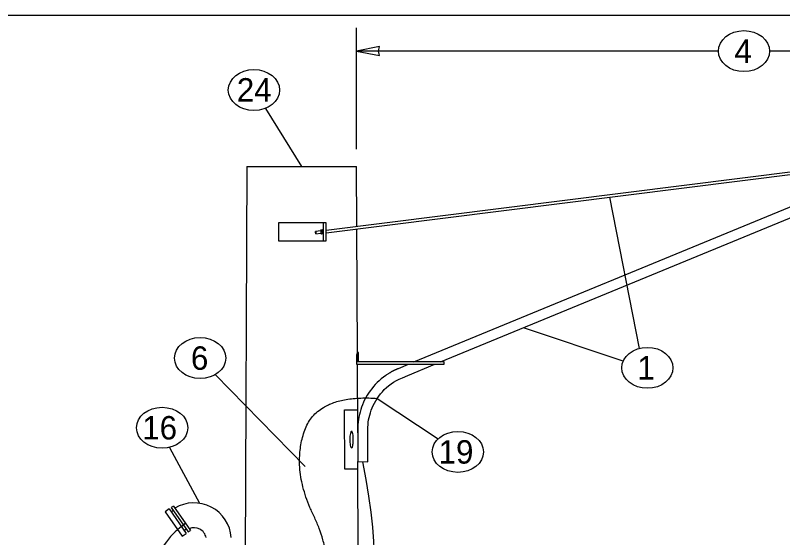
# Model space of a CAD drawing. Extents: x 99862 to 104211, y 98939 to 102076.
# Drawn here: x 100788 to 101312, y 101719 to 102076 of the extents above; entities that cross this region are included whole.
import ezdxf

# ---------------------------------------------------------------- set-up
doc = ezdxf.new("R2010")
doc.units = 0
for name, color, linetype in [('Level 1', 7, 'Continuous'), ('Level 12', 7, 'Continuous'), ('Level 15', 7, 'Continuous'), ('Level 20', 7, 'Continuous'), ('Level 32', 7, 'Continuous'), ('Level 33', 7, 'Continuous'), ('Level 34', 7, 'Continuous'), ('Level 49', 7, 'Continuous'), ('Level 7', 7, 'Continuous')]:
    doc.layers.add(name, color=color, linetype=linetype)

msp = doc.modelspace()

# ---------------------------------------------------------------- linework, layer by layer
at = {"layer": 'Level 1'}
for p, q in [((100946.45, 101972.17), (100944.21, 101433.5)), ((100946.45, 101972.17), (101021.45, 101972.17)), ((101021.62, 101931.09), (101021.45, 101972.17)), ((101021.98, 101844.89), (101021.63, 101929.52)), ((101022.23, 101790.32), (101022.01, 101837.13)), ((101023.69, 101433.5), (101022.29, 101770.61))]:
    msp.add_line(p, q, dxfattribs=at)
msp.add_lwpolyline([(99862, 99999.5), (103151, 99999.5), (103151, 102075.5), (99862, 102075.5)], close=True, dxfattribs=at)
at = {"layer": 'Level 12'}
for points, degree in [([(100904.57, 101673.7), (100910.32, 101636.13), (100995.02, 101627.02), (101007.07, 101702.96), (100977.17, 101764.49), (100993.88, 101816.64), (101035.56, 101813.83)], 2), ([(100904.2, 101728), (100894.95, 101721.58), (100879.91, 101703.82), (100865.23, 101628.33), (100967.11, 101591.05), (101052.01, 101637.94), (101025.75, 101770.54)], 3)]:
    msp.add_open_spline(points, degree=degree, dxfattribs=at)
at = {"layer": 'Level 15'}
for p, q in [((101021.45, 101984.17), (101021.45, 102067.04)), ((101268.47, 102051.04), (101021.45, 102051.04)), ((101548.64, 102051.04), (101303.47, 102051.04)), ((100959.2, 102011.93), (100983.95, 101972.17)), ((101214.6, 101848), (101194.38, 101951.23)), ((101203.48, 101839.29), (101135.49, 101862.09)), ((100924.99, 101830.05), (100986.33, 101767.3)), ((101035.56, 101813.83), (101077.14, 101786.19)), ((100893.81, 101780.37), (100914.12, 101742.12))]:
    msp.add_line(p, q, dxfattribs=at)
msp.add_lwpolyline([(101021.45, 102051.04), (101037.17, 102047.96), (101036.45, 102051.04), (101037.17, 102054.13)], close=True, dxfattribs=at)
at = {"layer": 'Level 20'}
for centre in [(101285.97, 102051.04), (100951.39, 102024.46), (100914.66, 101841.35), (101220.01, 101834.68), (100888.68, 101793.75), (101090.61, 101777.25)]:
    msp.add_ellipse(centre, major_axis=(-17.5, 0), ratio=0.8, dxfattribs=at)
at = {"layer": 'Level 32'}
for p, q in [((101060.66, 101838.69), (101373.4, 101967.79)), ((101078.79, 101838.69), (101378.62, 101962.46)), ((101050.13, 101834.34), (101056.88, 101837.13)), ((101056.55, 101829.51), (101075, 101837.13)), ((101052.77, 101827.95), (101056.55, 101829.51)), ((101022.23, 101792.5), (101022.24, 101787.89)), ((101029.21, 101770.48), (101029.14, 101792.52)), ((101022.29, 101770.61), (101029.21, 101770.48)), ((100896.36, 101740.24), (100894.96, 101739.28)), ((100896.36, 101740.24), (100907.98, 101723.51)), ((100893.57, 101738.31), (100890.78, 101736.37)), ((100890.78, 101736.37), (100902.4, 101719.64)), ((100893.57, 101738.31), (100905.19, 101721.57)), ((100894.96, 101739.28), (100906.58, 101722.54)), ((100896.42, 101737.18), (100895.02, 101736.22)), ((100903.73, 101723.66), (100905.13, 101724.63)), ((100902.4, 101719.64), (100905.19, 101721.57)), ((100902.4, 101719.64), (100902.4, 101719.64)), ((100905.19, 101721.57), (100905.19, 101721.57)), ((100906.58, 101722.54), (100907.98, 101723.51)), ((100906.58, 101722.54), (100906.58, 101722.54))]:
    msp.add_line(p, q, dxfattribs=at)
for radius, start, end in [(25.47, 3.8236, 120.9455), (8.49, 11.537, 113.2311)]:
    msp.add_arc((100910.45, 101716.96), radius, start, end, dxfattribs=at)
for points, degree in [([(101041.37, 101829.51), (101045.2, 101832.03), (101047.61, 101833.3), (101050.13, 101834.34)], 2), ([(101041.37, 101829.51), (101037.1, 101826.49), (101030.01, 101819.39), (101023.59, 101806.26), (101022.21, 101797.05), (101022.23, 101792.5)], 3), ([(101029.14, 101792.52), (101029.13, 101796.93), (101030.63, 101805.62), (101038.1, 101818.94), (101046.88, 101825.52), (101052.77, 101827.95)], 3), ([(101022.24, 101787.93), (101022.24, 101787.38), (101022.24, 101786.84), (101022.24, 101786.29), (101022.25, 101784), (101022.26, 101781.71), (101022.29, 101770.61)], 3)]:
    msp.add_open_spline(points, degree=degree, dxfattribs=at)
at = {"layer": 'Level 33'}
for p, q in [((101022.71, 101845.05), (101022.02, 101845.05)), ((101022.72, 101838.69), (101022.72, 101845.04)), ((101021.79, 101838.69), (101021.79, 101842.99)), ((101021.32, 101837.13), (101071.86, 101837.13)), ((101071.86, 101838.69), (101021.79, 101838.69)), ((101071.65, 101838.69), (101071.77, 101838.69)), ((101071.65, 101837.13), (101071.77, 101837.13)), ((101081.23, 101838.69), (101071.97, 101838.69)), ((101071.97, 101837.13), (101081.23, 101837.13)), ((101081.23, 101837.13), (101081.23, 101838.69))]:
    msp.add_line(p, q, dxfattribs=at)
msp.add_ellipse((100737.52, 101828.92), major_axis=(-581.56, 0), ratio=0.027734, start_param=4.201666, end_param=4.202627, dxfattribs=at)
for points, degree in [([(101021.62, 101844.12), (101021.53, 101843.82), (101021.42, 101843.44), (101021.3, 101843)], 2), ([(101021.98, 101845.02), (101022, 101845.04), (101022.01, 101845.05), (101022.04, 101845.05), (101022.03, 101845), (101021.96, 101844.83), (101021.9, 101844.69), (101021.76, 101844.4), (101021.7, 101844.27), (101021.62, 101844.12)], 3), ([(101021.79, 101842.99), (101022.1, 101843.66), (101022.35, 101844.18), (101022.59, 101844.7), (101022.65, 101844.83), (101022.72, 101845.01), (101022.73, 101845.05), (101022.71, 101845.05)], 3), ([(101021.3, 101843), (101021.31, 101841.04), (101021.31, 101839.08), (101021.32, 101837.13)], 2), ([(101022.57, 101841.27), (101022.57, 101841.24), (101022.57, 101841.21), (101022.58, 101841.18), (101022.58, 101841.14), (101022.58, 101841.1), (101022.58, 101841.06), (101022.58, 101841.02), (101022.59, 101840.97), (101022.59, 101840.93), (101022.59, 101840.89), (101022.58, 101840.84), (101022.58, 101840.8), (101022.58, 101840.76), (101022.58, 101840.72), (101022.58, 101840.68), (101022.57, 101840.65), (101022.57, 101840.62), (101022.57, 101840.6), (101022.56, 101840.57), (101022.56, 101840.55), (101022.55, 101840.54), (101022.55, 101840.53), (101022.54, 101840.53), (101022.54, 101840.54), (101022.53, 101840.54), (101022.53, 101840.55), (101022.52, 101840.57), (101022.52, 101840.59), (101022.52, 101840.62), (101022.51, 101840.65), (101022.51, 101840.68), (101022.5, 101840.72), (101022.5, 101840.76), (101022.5, 101840.8), (101022.5, 101840.84), (101022.5, 101840.89), (101022.5, 101840.93), (101022.5, 101840.98), (101022.5, 101841.02), (101022.5, 101841.06), (101022.5, 101841.11), (101022.51, 101841.14), (101022.51, 101841.18), (101022.51, 101841.21), (101022.52, 101841.24), (101022.52, 101841.25), (101022.52, 101841.26), (101022.52, 101841.27)], 3), ([(101022.52, 101842.47), (101022.52, 101842.5), (101022.52, 101842.52), (101022.52, 101842.54), (101022.52, 101842.56), (101022.52, 101842.59), (101022.53, 101842.6), (101022.53, 101842.62), (101022.53, 101842.64), (101022.53, 101842.65), (101022.53, 101842.66), (101022.54, 101842.67), (101022.54, 101842.68), (101022.54, 101842.68), (101022.54, 101842.68), (101022.55, 101842.68), (101022.55, 101842.68), (101022.55, 101842.67), (101022.55, 101842.66), (101022.56, 101842.65), (101022.56, 101842.64), (101022.56, 101842.62), (101022.56, 101842.6), (101022.56, 101842.58), (101022.56, 101842.56), (101022.57, 101842.54), (101022.57, 101842.52), (101022.57, 101842.49), (101022.57, 101842.49), (101022.57, 101842.48), (101022.57, 101842.47)], 3), ([(101022.52, 101841.27), (101022.52, 101841.37), (101022.52, 101841.47), (101022.52, 101841.57), (101022.52, 101841.87), (101022.52, 101842.17), (101022.52, 101842.47)], 3), ([(101022.57, 101842.47), (101022.57, 101842.17), (101022.57, 101841.87), (101022.57, 101841.57), (101022.57, 101841.47), (101022.57, 101841.37), (101022.57, 101841.27)], 3)]:
    msp.add_open_spline(points, degree=degree, dxfattribs=at)
at = {"layer": 'Level 34'}
for p, q in [((100998.62, 101933.77), (100968.1, 101933.77)), ((100968.1, 101933.77), (100968.1, 101921.56)), ((100998.62, 101933.77), (100998.62, 101921.56)), ((101000.65, 101933.77), (100998.62, 101933.77)), ((101000.65, 101921.56), (101000.65, 101933.77)), ((100968.1, 101921.56), (100998.62, 101921.56)), ((100998.62, 101921.56), (101000.65, 101921.56))]:
    msp.add_line(p, q, dxfattribs=at)
at = {"layer": 'Level 49'}
for p, q in [((101376.75, 101975.69), (101000.65, 101928.5)), ((101000.65, 101926.93), (101377.37, 101974.2)), ((100996.96, 101928.17), (100993.45, 101927.73)), ((100998.54, 101928.37), (100998.23, 101928.33)), ((100993.65, 101926.18), (100997.16, 101926.62)), ((100998.42, 101926.78), (100998.54, 101926.79)), ((101013.41, 101765.4), (101013.24, 101805.98)), ((101013.24, 101805.98), (101022.11, 101805.98)), ((101022.23, 101765.4), (101013.41, 101765.4))]:
    msp.add_line(p, q, dxfattribs=at)
msp.add_ellipse((100993.55, 101926.96), major_axis=(0.097, -0.775), ratio=0.101579, dxfattribs=at)
for points, degree in [([(100998.42, 101926.78), (100998.41, 101926.78), (100998.37, 101927.09), (100998.32, 101927.54), (100998.26, 101928), (100998.22, 101928.32), (100998.23, 101928.33)], 4), ([(101018.89, 101781.6), (101018.68, 101780.59), (101018.39, 101780.06), (101017.76, 101780.16), (101017.42, 101780.79), (101016.93, 101782.89), (101016.78, 101784.37), (101016.79, 101787.34), (101016.95, 101788.79), (101017.45, 101790.77), (101017.79, 101791.32), (101018.41, 101791.24), (101018.7, 101790.62), (101019.1, 101788.49), (101019.21, 101787.01), (101019.2, 101784.05), (101019.09, 101782.6), (101018.89, 101781.6)], 3)]:
    msp.add_open_spline(points, degree=degree, dxfattribs=at)
at = {"layer": 'Level 7'}
for p, q in [((100996.9, 101928.74), (100996.92, 101928.77)), ((100997.1, 101928.78), (100998.15, 101928.91)), ((100998.16, 101928.93), (100997.11, 101928.8)), ((100998.16, 101928.93), (100998.15, 101928.91)), ((100998.15, 101928.91), (100998.31, 101927.53)), ((100998.24, 101928.33), (100998.16, 101928.93)), ((100997.26, 101926.04), (100997.23, 101926.06)), ((100997.26, 101927.4), (100998.31, 101927.53)), ((100998.49, 101926.18), (100997.44, 101926.05)), ((100998.31, 101927.53), (100998.49, 101926.18)), ((100998.43, 101926.78), (100998.5, 101926.2)), ((100998.5, 101926.2), (100998.49, 101926.18))]:
    msp.add_line(p, q, dxfattribs=at)
msp.add_ellipse((100997.07, 101927.4), major_axis=(-0.17, 1.34), ratio=0.008672, start_param=0.009974, end_param=3.131717, dxfattribs=at)
for points, degree in [([(100997.11, 101928.8), (100997, 101928.78), (100996.92, 101928.77), (100996.92, 101928.76), (100996.99, 101928.77), (100997.1, 101928.78)], 3), ([(100997.1, 101928.78), (100997.06, 101928.66), (100997.03, 101928.54), (100996.99, 101928.31), (100996.98, 101928.19), (100997.03, 101927.83), (100997.13, 101927.61), (100997.26, 101927.4)], 3), ([(100997.26, 101927.4), (100997.22, 101927.29), (100997.19, 101927.17), (100997.16, 101926.94), (100997.15, 101926.82), (100997.2, 101926.47), (100997.3, 101926.25), (100997.44, 101926.05)], 3), ([(100997.44, 101926.05), (100997.34, 101926.04), (100997.26, 101926.03), (100997.26, 101926.04)], 2)]:
    msp.add_open_spline(points, degree=degree, dxfattribs=at)

# ---------------------------------------------------------------- texts
at = {"layer": 'Level 20'}
for s, p in [('4', (101279.46, 102043.04)), ('24', (100939.69, 102016.59)), ('6', (100908.35, 101833.36)), ('1', (101213.14, 101826.69)), ('16', (100875.08, 101785.75)), ('19', (101077.44, 101769.25))]:
    msp.add_text(s, height=16, dxfattribs=at).set_placement(p)

doc.saveas('drawing.dxf')
